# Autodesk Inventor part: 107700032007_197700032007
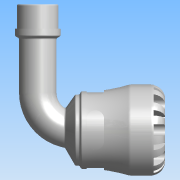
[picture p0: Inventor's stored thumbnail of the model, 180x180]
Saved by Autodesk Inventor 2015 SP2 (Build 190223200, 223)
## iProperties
Created: 2016-12
Part Number: 107700032007_197700032007
Material: PVC-Piping
Description: PLASSON 90° ELBOW WITH MALE INTEGRAL BRASS 32X3/4" SERIES 1
Document SubType Name: Modeling
Designer: KIM
Mass: 664.223 g
Surface Area: 733.008 cm^2
Volume: 474.445 cm^3
Density: 1.4 g/cm^3
Appearance: Smooth - White
Author: KIM
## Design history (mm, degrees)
derived "1077.ipt"
feature "Solid1::1077.ipt"
tag "TaggingFeature1"
body "Solid1"
other parameters: "d1" = 22.68, "d2" = 32, "d4" = 58, "d8" = 49.3, "d13" = 7.2, "d14" = 7.2, "d15" = 0, "d17" = 360 deg, "d19" = 8 deg, "d20" = 0.64, "d21" = 0.64, "d22" = 8 deg, "d24" = 0, "d26" = 360 deg, "d33" = 5.8, "d43" = 45.24, "d51" = 0.58, "d54" = 11.2, "d55" = 7.04, "d57" = 14.112, "d58" = 0, "d74" = 0, "d78" = 54, "d82" = 0.64, "d115" = 360 deg, "d207" = 90 deg, "d228" = 9.52, "d247" = 1.16, "d248" = 3.24, "d268" = 27.115, "d269" = 3.24, "d270" = 81, "d276" = 26.441, "d277" = 15.5, "d278" = 29.0851, "d280" = 20.15, "d281" = 3.96615, "d283" = 23.7969, "d286" = 0, "d287" = 0, "d288" = 18.5087, "d290" = 10.72155, "d292" = 30 deg, "d294" = 2.6441, "d296" = 30 deg, "d_" = 32, "E_" = 58, "l_" = 54, "A_" = 81, "l_2" = 15.5, "R_" = 26.441, "d9" = 9, "d11" = 58, "d289" = 18.5087
